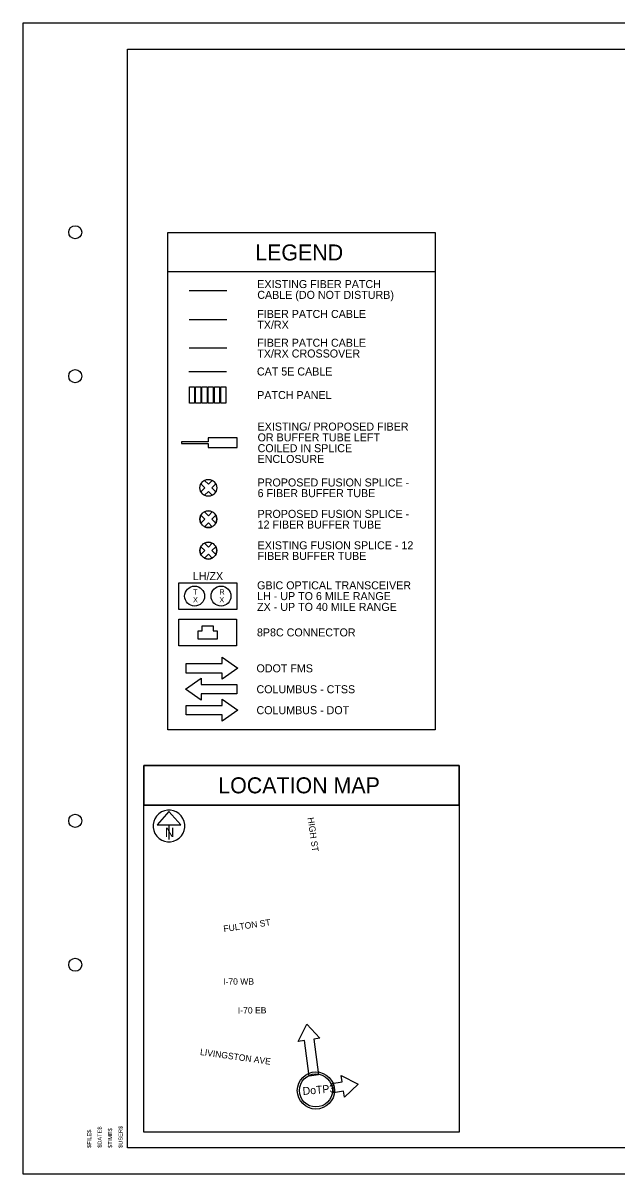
# Model space of a CAD drawing. Extents: x 1805893 to 1833564, y 708898 to 716199.
# Drawn here: x 1832103.1 to 1832330.3, y 714257.9 to 714697.9 of the extents above; entities that cross this region are included whole.
import ezdxf

# ---------------------------------------------------------------- set-up
doc = ezdxf.new("R2010")
doc.units = 0
for name, color, linetype in [('BR_X_Slab_Object', 7, 'Continuous'), ('SH_Border', 7, 'Continuous'), ('SH_Cut_Line', 7, 'Continuous'), ('SH_Data', 7, 'Continuous'), ('SH_Text', 7, 'Continuous'), ('UT_X_Misc_Cells', 7, 'Continuous')]:
    doc.layers.add(name, color=color, linetype=linetype)

msp = doc.modelspace()

# ---------------------------------------------------------------- linework, layer by layer
at = {"layer": 'SH_Border'}
msp.add_lwpolyline([(1832143.13, 714687.91), (1832773.13, 714687.91), (1832773.13, 714267.91), (1832143.13, 714267.91)], close=True, dxfattribs=at)
for centre in [(1832123.13, 714617.91), (1832123.13, 714562.91), (1832123.13, 714392.91), (1832123.13, 714337.91)]:
    msp.add_circle(centre, 2.5, dxfattribs=at)
at = {"layer": 'SH_Cut_Line'}
msp.add_lwpolyline([(1832103.13, 714257.91), (1832783.13, 714257.91), (1832783.13, 714697.91), (1832103.13, 714697.91)], close=True, dxfattribs=at)
at = {"layer": 'SH_Data'}
for p, q in [((1832166.73, 714595.63), (1832181.07, 714595.63)), ((1832166.73, 714584.63), (1832181.07, 714584.63)), ((1832172.68, 714520.23), (1832171.19, 714521.72)), ((1832171.19, 714521.72), (1832172.68, 714520.23)), ((1832174.03, 714521.58), (1832172.54, 714523.08)), ((1832174.03, 714521.58), (1832172.54, 714523.08)), ((1832174.03, 714521.58), (1832175.53, 714523.08)), ((1832175.53, 714523.08), (1832174.03, 714521.58)), ((1832175.39, 714520.23), (1832176.88, 714521.72)), ((1832175.39, 714520.23), (1832176.88, 714521.72)), ((1832171.19, 714518.74), (1832172.68, 714520.23)), ((1832172.68, 714520.23), (1832171.19, 714518.74)), ((1832172.54, 714517.38), (1832174.03, 714518.87)), ((1832172.54, 714517.38), (1832174.03, 714518.87)), ((1832175.53, 714517.38), (1832174.03, 714518.87)), ((1832174.03, 714518.87), (1832175.53, 714517.38)), ((1832176.88, 714518.74), (1832175.39, 714520.23)), ((1832176.88, 714518.74), (1832175.39, 714520.23)), ((1832172.68, 714508.22), (1832171.19, 714509.71)), ((1832172.68, 714508.22), (1832171.19, 714509.71)), ((1832171.19, 714506.73), (1832172.68, 714508.22)), ((1832171.19, 714506.73), (1832172.68, 714508.22)), ((1832174.03, 714509.57), (1832172.54, 714511.07)), ((1832172.54, 714511.07), (1832174.03, 714509.57)), ((1832174.03, 714509.57), (1832175.53, 714511.07)), ((1832174.03, 714509.57), (1832175.53, 714511.07)), ((1832175.39, 714508.22), (1832176.88, 714509.71)), ((1832176.88, 714509.71), (1832175.39, 714508.22)), ((1832176.88, 714506.73), (1832175.39, 714508.22)), ((1832175.39, 714508.22), (1832176.88, 714506.73)), ((1832172.54, 714505.37), (1832174.03, 714506.86)), ((1832174.03, 714506.86), (1832172.54, 714505.37)), ((1832175.53, 714505.37), (1832174.03, 714506.86)), ((1832175.53, 714505.37), (1832174.03, 714506.86)), ((1832174.03, 714497.57), (1832172.54, 714499.06)), ((1832172.54, 714499.06), (1832174.03, 714497.57)), ((1832174.03, 714497.57), (1832175.53, 714499.06)), ((1832174.03, 714497.57), (1832175.53, 714499.06)), ((1832172.68, 714496.21), (1832171.19, 714497.71)), ((1832172.68, 714496.21), (1832171.19, 714497.71)), ((1832171.19, 714494.72), (1832172.68, 714496.21)), ((1832171.19, 714494.72), (1832172.68, 714496.21)), ((1832172.54, 714493.37), (1832174.03, 714494.86)), ((1832174.03, 714494.86), (1832172.54, 714493.37)), ((1832175.53, 714493.37), (1832174.03, 714494.86)), ((1832175.53, 714493.37), (1832174.03, 714494.86)), ((1832175.39, 714496.21), (1832176.88, 714497.71)), ((1832176.88, 714497.71), (1832175.39, 714496.21)), ((1832176.88, 714494.72), (1832175.39, 714496.21)), ((1832175.39, 714496.21), (1832176.88, 714494.72)), ((1832179.31, 714453.02), (1832179.31, 714455.42)), ((1832165.58, 714453.02), (1832179.31, 714453.02)), ((1832165.58, 714449.42), (1832165.58, 714453.02)), ((1832179.31, 714449.42), (1832165.58, 714449.42)), ((1832171.24, 714447.42), (1832171.24, 714445.02)), ((1832179.31, 714447.02), (1832179.31, 714449.42)), ((1832171.24, 714445.02), (1832184.98, 714445.02)), ((1832184.98, 714441.42), (1832171.24, 714441.42)), ((1832171.24, 714441.42), (1832171.24, 714439.02)), ((1832184.98, 714445.02), (1832184.98, 714441.42)), ((1832165.58, 714437.02), (1832179.31, 714437.02)), ((1832165.58, 714433.42), (1832165.58, 714437.02)), ((1832179.31, 714437.02), (1832179.31, 714439.42)), ((1832179.31, 714433.42), (1832165.58, 714433.42)), ((1832179.31, 714431.02), (1832179.31, 714433.42))]:
    msp.add_line(p, q, dxfattribs=at)
for points in [[(1832158.57, 714617.86), (1832260.8, 714617.86), (1832260.8, 714602.75), (1832158.57, 714602.75)], [(1832260.8, 714617.86), (1832260.8, 714427.7), (1832158.57, 714427.7), (1832158.57, 714617.86)], [(1832168.74, 714558.81), (1832168.74, 714552.56), (1832166.78, 714552.56), (1832166.78, 714558.81)], [(1832171.14, 714558.81), (1832171.14, 714552.56), (1832169.18, 714552.56), (1832169.18, 714558.81)], [(1832173.53, 714558.81), (1832173.53, 714552.56), (1832171.57, 714552.56), (1832171.57, 714558.81)], [(1832175.93, 714558.81), (1832175.93, 714552.56), (1832173.97, 714552.56), (1832173.97, 714558.81)], [(1832178.32, 714558.81), (1832178.32, 714552.56), (1832176.36, 714552.56), (1832176.36, 714558.81)], [(1832180.72, 714558.81), (1832180.72, 714552.56), (1832178.76, 714552.56), (1832178.76, 714558.81)], [(1832162.78, 714483.95), (1832184.88, 714483.95), (1832184.88, 714473.7), (1832162.78, 714473.7)], [(1832162.73, 714470.07), (1832184.82, 714470.07), (1832184.82, 714459.82), (1832162.73, 714459.82)], [(1832270.01, 714414.04), (1832149.37, 714414.04), (1832149.37, 714398.93), (1832270.01, 714398.93)], [(1832270.01, 714398.93), (1832149.37, 714398.93), (1832149.37, 714414.04), (1832270.01, 714414.04)], [(1832270.01, 714398.93), (1832270.01, 714273.91), (1832149.37, 714273.91), (1832149.37, 714398.93)], [(1832270.01, 714398.93), (1832270.01, 714273.91), (1832149.37, 714273.91), (1832149.37, 714398.93)], [(1832270.01, 714398.93), (1832270.01, 714273.91), (1832149.37, 714273.91), (1832149.37, 714398.93)], [(1832270.01, 714398.93), (1832270.01, 714273.91), (1832149.37, 714273.91), (1832149.37, 714398.93)], [(1832270.01, 714398.93), (1832270.01, 714273.91), (1832149.37, 714273.91), (1832149.37, 714398.93)]]:
    msp.add_lwpolyline(points, close=True, dxfattribs=at)
for points in [[(1832181.1, 714573.63), (1832166.73, 714573.63), (1832166.73, 714573.63), (1832166.73, 714573.63)], [(1832166.6, 714564.69), (1832180.94, 714564.72), (1832180.94, 714564.72)], [(1832163.74, 714537.75), (1832163.74, 714537.45), (1832163.74, 714537.14), (1832174.02, 714537.14), (1832174.02, 714535.61), (1832185.07, 714535.61), (1832185.07, 714539.28), (1832174.02, 714539.28), (1832174.02, 714537.75), (1832163.74, 714537.75)], [(1832185.07, 714535.61), (1832185.07, 714539.28), (1832174.02, 714539.28), (1832174.02, 714537.75), (1832163.74, 714537.75), (1832163.74, 714537.45), (1832163.74, 714537.14), (1832174.02, 714537.14), (1832174.02, 714535.61), (1832185.07, 714535.61)], [(1832175.9, 714465.55), (1832177.41, 714465.55), (1832177.41, 714462.32), (1832170.14, 714462.32), (1832170.14, 714465.55), (1832171.65, 714465.55)], [(1832171.65, 714465.55), (1832171.65, 714467.46), (1832175.9, 714467.46), (1832175.9, 714465.55)], [(1832179.31, 714455.42), (1832185.31, 714451.22), (1832179.31, 714447.02)], [(1832171.24, 714439.02), (1832165.24, 714443.22), (1832171.24, 714447.42)], [(1832179.31, 714439.42), (1832185.31, 714435.22), (1832179.31, 714431.02)]]:
    msp.add_lwpolyline(points, dxfattribs=at)
for centre, radius in [((1832174.03, 714520.23), 3.22), ((1832174.03, 714508.22), 3.22), ((1832174.03, 714496.21), 3.22), ((1832168.78, 714478.83), 3.81), ((1832178.88, 714478.83), 3.81)]:
    msp.add_circle(centre, radius, dxfattribs=at)
for centre, start, end in [((1832174.03, 714520.23), 117.647, 152.353), ((1832174.03, 714520.23), 27.647, 62.353), ((1832174.03, 714520.23), 207.647, 242.353), ((1832174.03, 714520.23), 297.647, 332.353), ((1832174.03, 714508.22), 152.353, 207.647), ((1832174.03, 714508.22), 62.353, 117.647), ((1832174.03, 714508.22), 332.353, 27.647), ((1832174.03, 714508.22), 242.353, 297.647), ((1832174.03, 714496.21), 62.353, 117.647), ((1832174.03, 714496.21), 152.353, 207.647), ((1832174.03, 714496.21), 332.353, 27.647), ((1832174.03, 714496.21), 242.353, 297.647)]:
    msp.add_arc(centre, 3.22, start, end, dxfattribs=at)
at = {"layer": 'SH_Text'}
for p, q in [((1832158.97, 714396.42), (1832154.46, 714391.42)), ((1832163.47, 714391.42), (1832158.97, 714396.42)), ((1832154.46, 714391.42), (1832163.47, 714391.42)), ((1832158.97, 714391.42), (1832158.97, 714385.76)), ((1832216.71, 714309.77), (1832214.33, 714309.44)), ((1832214.33, 714309.44), (1832216.22, 714295.83)), ((1832210.76, 714308.94), (1832208.39, 714308.61)), ((1832212.66, 714295.34), (1832210.76, 714308.94)), ((1832216.22, 714295.83), (1832212.66, 714295.34)), ((1832221.29, 714292.53), (1832225.16, 714293.14)), ((1832221.85, 714288.97), (1832221.29, 714292.53)), ((1832225.16, 714293.14), (1832224.79, 714295.51)), ((1832225.72, 714289.59), (1832221.85, 714288.97)), ((1832226.1, 714287.22), (1832225.72, 714289.59))]:
    msp.add_line(p, q, dxfattribs=at)
for points in [[(1832208.39, 714308.61), (1832211.72, 714315.13), (1832216.71, 714309.77)], [(1832224.79, 714295.51), (1832231.37, 714292.3), (1832226.1, 714287.22)]]:
    msp.add_lwpolyline(points, dxfattribs=at)
for radius in [7.11, 6.31]:
    msp.add_circle((1832215.17, 714289.83), radius, dxfattribs=at)
msp.add_arc((1832158.97, 714390.95), 6.08, 129.7798, 129.7633, dxfattribs=at)

# ---------------------------------------------------------------- texts
at = {"layer": 'BR_X_Slab_Object'}
for s, p in [('T', (1832168.17, 714479.43)), ('R', (1832178.27, 714479.43)), ('X', (1832168.18, 714476.43)), ('X', (1832178.27, 714476.43))]:
    msp.add_text(s, height=2, rotation=0.0475, dxfattribs=at).set_placement(p)
at = {"layer": 'SH_Data'}
for s, height, p in [('LEGEND', 6.119, (1832191.95, 714607.14)), ('EXISTING FIBER PATCH ', 3.0596, (1832192.75, 714596.58)), ('CABLE (DO NOT DISTURB)', 3.0596, (1832192.75, 714592.46)), ('FIBER PATCH CABLE', 3.0596, (1832192.75, 714585.16)), ('TX/RX', 3.06, (1832192.75, 714581.04)), ('TX/RX CROSSOVER', 3.0596, (1832192.75, 714570.04)), ('FIBER PATCH CABLE', 3.0596, (1832192.75, 714574.16)), ('CAT 5E CABLE', 3.0596, (1832192.61, 714563.16)), ('PATCH PANEL', 3.0596, (1832192.73, 714554.16)), ('EXISTING/ PROPOSED FIBER ', 3.0596, (1832192.87, 714542.1)), ('OR BUFFER TUBE LEFT ', 3.0596, (1832192.87, 714537.98)), ('COILED IN SPLICE ', 3.0596, (1832192.87, 714533.85)), ('ENCLOSURE', 3.06, (1832192.87, 714529.73)), ('PROPOSED FUSION SPLICE - ', 3.0596, (1832192.88, 714520.74)), ('6 FIBER BUFFER TUBE', 3.0596, (1832192.88, 714516.66)), ('PROPOSED FUSION SPLICE - ', 3.0596, (1832192.88, 714508.73)), ('12 FIBER BUFFER TUBE', 3.0596, (1832192.88, 714504.65)), ('EXISTING FUSION SPLICE - 12 ', 3.0596, (1832192.88, 714496.72)), ('FIBER BUFFER TUBE', 3.0596, (1832192.88, 714492.65)), ('LH/ZX', 3.06, (1832168.1, 714484.95)), ('GBIC OPTICAL TRANSCEIVER', 3.0596, (1832192.68, 714481.42)), ('LH - UP TO 6 MILE RANGE', 3.0596, (1832192.68, 714477.3)), ('ZX - UP TO 40 MILE RANGE', 3.0596, (1832192.68, 714473.17)), ('8P8C CONNECTOR', 3.0596, (1832192.62, 714463.42)), ('ODOT FMS', 3.06, (1832192.45, 714449.69)), ('COLUMBUS - CTSS', 3.0596, (1832192.45, 714441.69)), ('COLUMBUS - DOT', 3.0596, (1832192.45, 714433.69)), ('LOCATION MAP', 6.1191, (1832177.82, 714403.43))]:
    msp.add_text(s, height=height, dxfattribs=at).set_placement(p)
at = {"layer": 'SH_Text'}
for s, height, rotation, p in [('HIGH ST', 2.448, 278.061, (1832211.97, 714394.08)), ('N', 3.66, 360, (1832157.45, 714386.68)), ('FULTON ST', 2.448, 8.061, (1832179.98, 714350.41)), ('I-70 WB', 2.448, 0.3445, (1832179.69, 714330.24)), ('I-70 EB', 2.448, 0.3445, (1832185.34, 714319.23)), ('LIVINGSTON AVE', 2.4477, 352.086, (1832170.75, 714303.41)), ('DoTP3', 3, 5, (1832210.23, 714288.1))]:
    msp.add_text(s, height=height, rotation=rotation, dxfattribs=at).set_placement(p)
at = {"layer": 'UT_X_Misc_Cells'}
for s, p in [('$FILE$', (1832129.23, 714267.91)), ('$DATE$', (1832133.23, 714267.91)), ('$TIME$', (1832137.23, 714267.91)), ('$USER$', (1832141.23, 714267.91))]:
    msp.add_text(s, height=1.56, rotation=90, dxfattribs=at).set_placement(p)

doc.saveas('drawing.dxf')
